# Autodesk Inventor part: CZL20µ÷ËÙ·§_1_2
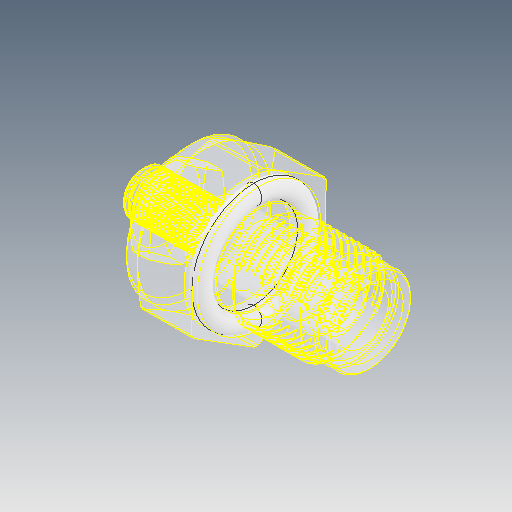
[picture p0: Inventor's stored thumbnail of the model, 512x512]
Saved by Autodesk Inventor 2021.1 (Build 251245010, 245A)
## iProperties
Created: 2021-05
Part Number: CZL20µ÷ËÙ·§_1_2
Material: Ogólny
Document SubType Name: Modeling
Designer: user
Density: 1 g/cm^3
Appearance: Domyślna
Author: user
Revision Number: ÈÎºÎ
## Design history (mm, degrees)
feature "NONE"
feature "Złożony1"
node "Bryła1"
body "Srf1"
